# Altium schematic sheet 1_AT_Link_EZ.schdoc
size 309 x 223 mm; Symbol: Artery_A4; Device: Artery_A4; Company: Artery Technology; Drawed: SD; Version: 1.4; Page Size: A4; @Project Name: AT-START-F402; @Page Count: 4; @Update Date: 2023-06-16; @Create Date: 2023-05-06; @Schematic Name: AT-START-F402; @Page No: 1; @Page Name: AT_Link_EZ
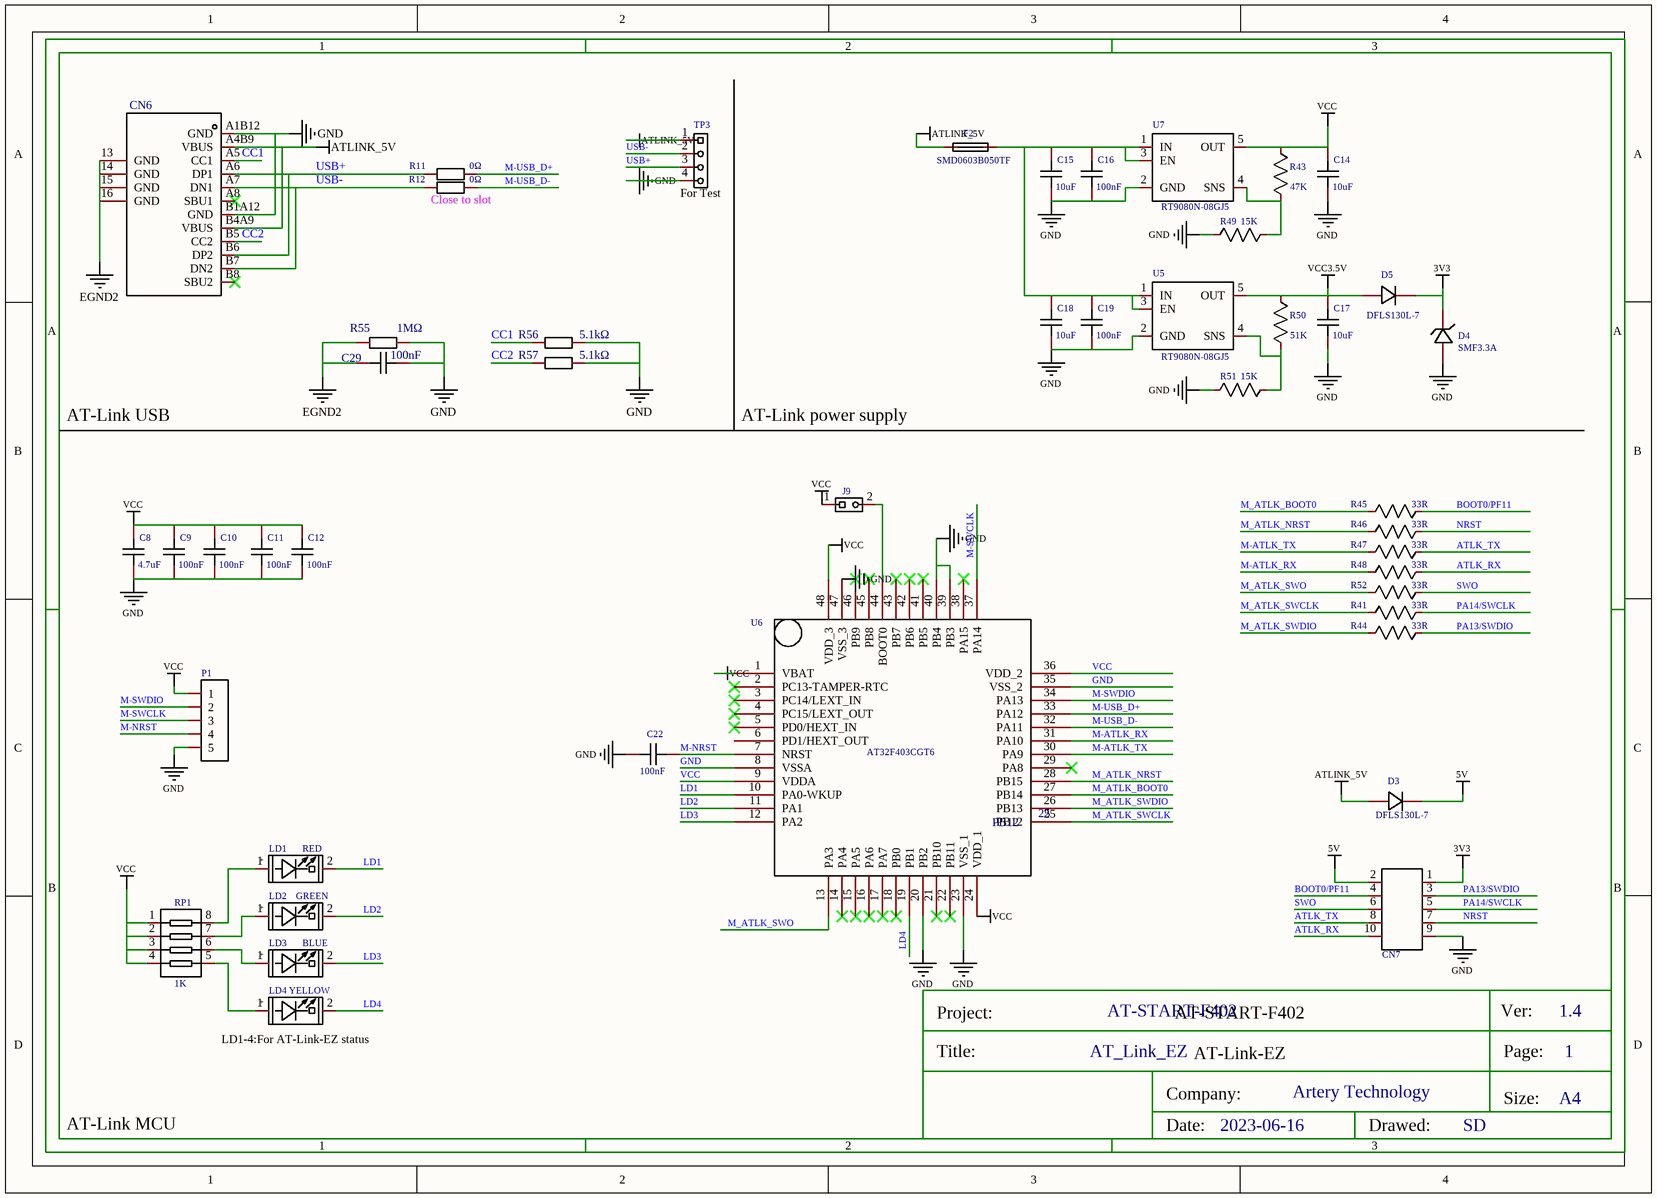
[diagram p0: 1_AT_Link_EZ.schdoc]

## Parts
C8  4.7uF  [0603_C-M]
C9  100nF  [C0603]
C10  100nF  [C0603]
C11  100nF  [C0603]
C12  100nF  [C0603]
C14  10uF  [C0603]
C15  10uF  [C0603]
C16  100nF  [C0603]
C17  10uF  [C0603]
C18  10uF  [C0603]
C19  100nF  [C0603]
C22  100nF  [C0603]
C29  value 100nF  [C0603]  (hidden comment: CC0603KRX7R9BB104)
CN6  TYPEC-304-BCP16  [USB-C-SMD_TYPEC-304-BCP16]  (value not drawn)
CN7  CON1  [HDR2X5]  (value not drawn)
D3  DFLS130L-7  [POWERDI-123_L2.8-W1.8-LS3.7-RD]
D4  SMF3.3A  [SOD-123_L2.8-W1.8-LS3.7-RD]
D5  DFLS130L-7  [POWERDI-123_L2.8-W1.8-LS3.7-RD]
F2  SMD0603B050TF  [R0603]
J9  1X2P,Male,DIP_2.54  [HDR1X2]  (value not drawn)
LD1  RED  [LED0603]
LD2  GREEN  [LED0603]
LD3  BLUE  [LED0603]
LD4  YELLOW  [LED0603]
P1  HDR-M-2.54_1x5  [HDR-M-2.54_1X5]  (value not drawn)
R11  0Ω  [R0603]
R12  0Ω  [R0603]
R41  33R  [0603_R-M]
R43  47K  [0603_R-M]
R44  33R  [0603_R-M]
R45  33R  [0603_R-M]
R46  33R  [0603_R-M]
R47  33R  [0603_R-M]
R48  33R  [0603_R-M]
R49  15K  [0603_R-M]
R50  51K  [0603_R-M]
R51  15K  [0603_R-M]
R52  33R  [0603_R-M]
R55  value 1MΩ  [R0603]  (hidden comment: RC0603FR-071ML)
R56  value 5.1kΩ  [R0603]  (hidden comment: 0603WAF5101T5E)
R57  value 5.1kΩ  [R0603]  (hidden comment: 0603WAF5101T5E)
RP1  1K  [0603*4,8P4R]
TP3  1X4P_2.54F  [HDR1X4 - TOP]  (value not drawn)
U5  RT9080N-08GJ5  [SOT-23-5]
U6  NAME: PB12  NUMBER: 25  [LQFP48 - 2]  (hidden comment: AT32F403CGT6)
U7  RT9080N-08GJ5  [SOT-23-5]

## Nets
3V3: CN7.1 D4.1 D5.1
5V: CN7.2 D3.1
ATLINK_5V: CN6.A4B9(VBUS) CN6.B4A9(VBUS) D3.2 F2.1 TP3.1
EGND2: C29.2 CN6.13(GND) CN6.14(GND) CN6.15(GND) CN6.16(GND) R55.1
GND: C8.2 C9.2 C10.2 C11.2 C12.2 C14.2 C15.2 C16.2 C17.2 C18.2 C19.2 C22.2 C29.1 CN6.A1B12(GND) CN6.B1A12(GND) CN7.9 D4.2 P1.5 R49.2 R51.2 R55.2 R56.2 R57.2 TP3.4 U5.2(GND) U6.8(VSSA) U6.20(PB2) U6.23(VSS_1) U6.35(VSS_2) U6.39(PB3) U6.40(PB4) U6.47(VSS_3) U7.2(GND)
VCC: C8.1 C9.1 C10.1 C11.1 C12.1 C14.1 J9.1 P1.1 R43.2 RP1.1 RP1.2 RP1.3 RP1.4 U6.1(VBAT) U6.9(VDDA) U6.24(VDD_1) U6.36(VDD_2) U6.48(VDD_3) U7.5(OUT)
VCC3.5V: C17.1 D5.2 R50.2 U5.5(OUT)
ATLK_RX: CN7.10 R48.1
ATLK_TX: CN7.8 R47.1
BOOT0/PF11: CN7.4 R45.1
CC1: CN6.A5(CC1) R56.1
CC2: CN6.B5(CC2) R57.1
LD1: LD1.2(CATHODE) U6.10(PA0-WKUP)
LD2: LD2.2(CATHODE) U6.11(PA1)
LD3: LD3.2(CATHODE) U6.12(PA2)
LD4: LD4.2(CATHODE) U6.19(PB1)
M-ATLK_RX: R48.2 U6.31(PA10)
M-ATLK_TX: R47.2 U6.30(PA9)
M-NRST: C22.1 P1.4 U6.7(NRST)
M-SWCLK: P1.3 U6.37(PA14)
M-SWDIO: P1.2 U6.34(PA13)
M-USB_D+: R11.2 U6.33(PA12)
M-USB_D-: R12.2 U6.32(PA11)
M_ATLK_BOOT0: R45.2 U6.27(PB14)
M_ATLK_NRST: R46.2 U6.28(PB15)
M_ATLK_SWCLK: R41.2 U6.25(PB12)
M_ATLK_SWDIO: R44.2 U6.26(PB13)
M_ATLK_SWO: R52.2 U6.13(PA3)
NRST: CN7.7 R46.1
PA13/SWDIO: CN7.3 R44.1
PA14/SWCLK: CN7.5 R41.1
SWO: CN7.6 R52.1
USB+: CN6.A6(DP1) CN6.B6(DP2) R11.1 TP3.3
USB-: CN6.A7(DN1) CN6.B7(DN2) R12.1 TP3.2
NetC15_1: C15.1 C16.1 C18.1 C19.1 F2.2 U5.1(IN) U5.3(EN) U7.1(IN) U7.3(EN)
NetJ9_2: J9.2 U6.44(BOOT0)
NetLD1_1: LD1.1(ANODE) RP1.8
NetLD2_1: LD2.1(ANODE) RP1.7
NetLD3_1: LD3.1(ANODE) RP1.6
NetLD4_1: LD4.1(ANODE) RP1.5
NetR43_1: R43.1 R49.1 U7.4(SNS)
NetR50_1: R50.1 R51.1 U5.4(SNS)

Not connected (* = marked no-connect by the designer): CN6 A8(SBU1)* B8(SBU2)*; U6 2(PC13-TAMPER-RTC)* 3(PC14/LEXT_IN)* 4(PC15/LEXT_OUT)* 5(PD0/HEXT_IN)* 6(PD1/HEXT_OUT) 14(PA4)* 15(PA5)* 16(PA6)* 17(PA7)* 18(PB0)* 21(PB10)* 22(PB11)* 29(PA8)* 38(PA15)* 41(PB5)* 42(PB6)* 43(PB7)* 45(PB8)* 46(PB9)*

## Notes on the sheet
- (near R12) Close to slot
- (near TP3) For Test
- AT-Link USB
- AT-Link power supply
- (near LD4) LD1-4:For AT-Link-EZ status
- AT-Link-EZ
- AT-START-F402
- AT-Link MCU

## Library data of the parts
C8 = 4.7uF: Convert to PCB: yes
C9-C12 C16 C19 C22 = CC0603KRX7R9BB104: 容值:100nF;精度:±10%;额定电压:50V;材质(温度系数):X7R;; Manufacturer: YAGEO(国巨); Add into BOM: yes; Tolerance: ±10%; Voltage Rated: 50V; Temperature Coefficient: X7R; Origin Footprint: 0603_C-M
C14 C15 C17 C18 = CL10A106KP8NNNC: 容值:10uF;精度:±10%;额定电压:10V;材质(温度系数):X5R;; Manufacturer: SAMSUNG(三星); Add into BOM: yes; Tolerance: ±10%; Voltage Rated: 10V; Temperature Coefficient: X5R; Origin Footprint: 0603_C-M
C29 = CC0603KRX7R9BB104: 容值:100nF;精度:±10%;额定电压:50V;温度系数:X7R;; Manufacturer: YAGEO(国巨); Add into BOM: yes; Tolerance: ±10%; Voltage Rated: 50V; Temperature Coefficient: X7R
CN6 = TYPEC-304-BCP16: 连接器类型:Type-C;标准:USB 3.1;公母:母座;触点数量:16.0;端口数量:1;安装方式:卧贴;额定电流 - 电源:3A;工作温度范围:-25~+85;焊接温度(最大值):260;; Manufacturer: XUNPU(讯普); Add into BOM: yes; Connector Type: Type-C; Gender: 母座; Number of Contacts: 16.0; Number of Ports: 1; Mounting Sytle: 卧贴; Current Rating - Power (Max): 3A; Welding Temperature (Max): 260
CN7 = CON1: Convert to PCB: yes
D3 D5 = DFLS130L-7: Manufacturer: Diodes Incorporated; Paste Type: expand; Convert to PCB: yes
D4 = SMF3.3A: Manufacturer: DOWO; Paste Type: expand; Convert to PCB: yes
F2 = SMD0603B035TF: Manufacturer: Brightking Elec (TAIWAN); Paste Type: expand; Convert to PCB: yes
J9 = 1X2P,Male,DIP_2.54: Convert to PCB: yes
LD1 = RED: Convert to PCB: yes
LD2 = GREEN: Convert to PCB: yes
LD3 = BLUE: Convert to PCB: yes
LD4 = YELLOW: Convert to PCB: yes
P1 = HDR-M-2.54_1x5: Convert to PCB: yes
R11 R12 = 0603WAF0000T5E: 电阻类型:厚膜电阻;阻值:0Ω;精度:±1%;功率:100mW;; Manufacturer: UNI-ROYAL(厚声); Add into BOM: yes; Tolerance: ±1%; Power(Watts): 100mW; Overload Voltage (Max): 75V; Origin Footprint: 0603_R-M
R41 R44-R48 R52 = 33R: Convert to PCB: yes
R43 = 47K: Convert to PCB: yes
R49 R51 = 15K: Convert to PCB: yes
R50 = 51K: Convert to PCB: yes
R55 = RC0603FR-071ML: 阻值:1MΩ;精度:±1%;功率:100mW;温度系数:±100ppm/;最大工作电压:75V;工作温度范围:-55~+155;; Manufacturer: YAGEO(国巨); Add into BOM: yes; Tolerance: ±1%; Power(Watts): 100mW; Overload Voltage (Max): 75V
R56 R57 = 0603WAF5101T5E: 电阻类型:厚膜电阻;阻值:5.1kΩ;精度:±1%;功率:1/10W;温度系数:±100ppm/;最大工作电压:75V;工作温度范围:-55~+155;; Manufacturer: UNI-ROYAL(厚声); Add into BOM: yes; Tolerance: ±1%; Power(Watts): 1/10W; Overload Voltage (Max): 75V
RP1 = 1K: Convert to PCB: yes
TP3 = 1X4P_2.54F: Convert to PCB: yes
U5 U7 = RT9080N-08GJ5: Convert to PCB: yes
U6 = AT32F403CGT6: Convert to PCB: yes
